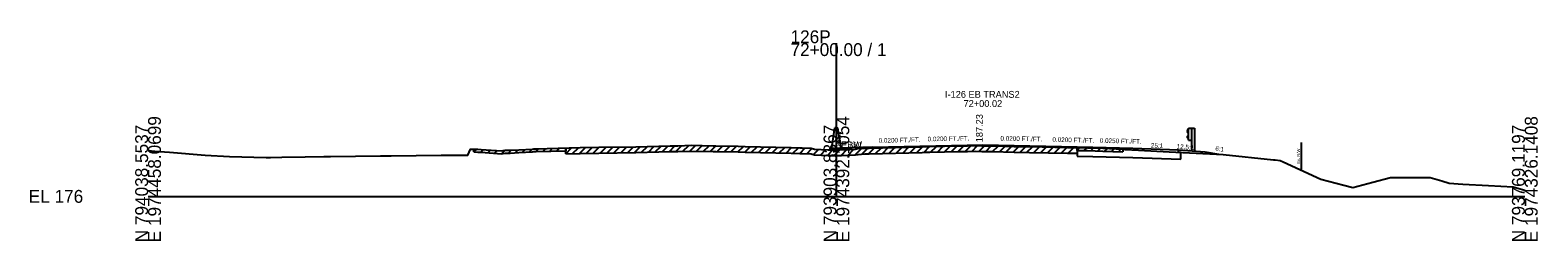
# Model space of a CAD drawing. Extents: x -161 to 1970889, y -4362 to 797231.
# Drawn here: x 2974.3 to 3302.8, y 4490.3 to 4536.2 of the extents above; entities that cross this region are included whole.
import ezdxf

# ---------------------------------------------------------------- set-up
doc = ezdxf.new("R2010")
doc.units = 0
for name, color, linetype in [('RD_GPK_XS_Cell', 7, 'Continuous'), ('RD_XS_Base', 7, 'Continuous'), ('RD_XS_EarthShd', 7, 'Continuous'), ('RD_XS_ExGround', 7, 'Continuous'), ('RD_XS_ExPaveRet', 7, 'Continuous'), ('RD_XS_ExRW', 7, 'Continuous'), ('RD_XS_GR', 7, 'Continuous'), ('RD_XS_MedBWall', 7, 'Continuous'), ('RD_XS_Misc_Line', 7, 'Continuous'), ('RD_XS_Pave', 7, 'Continuous'), ('RD_XS_PaveOvlay', 7, 'Continuous'), ('RD_XS_PaveShd', 7, 'Continuous'), ('RD_XS_TieSlope', 7, 'Continuous'), ('RD_XS_TX_Elev_EX', 7, 'Continuous'), ('RD_XS_TX_Elev_PR', 7, 'Continuous'), ('RD_XS_TX_MkPT', 7, 'Continuous'), ('RD_XS_TX_Profile', 7, 'Continuous'), ('RD_XS_TX_ShdSlope', 7, 'Continuous'), ('RD_XS_TX_Slope', 7, 'Continuous'), ('RD_XS_TX_Station', 7, 'Continuous')]:
    doc.layers.add(name, color=color, linetype=linetype)

msp = doc.modelspace()

# ---------------------------------------------------------------- linework, layer by layer
at = {"layer": 'RD_GPK_XS_Cell'}
for p, q in [((3150, 4500), (3150, 4533.38)), ((3000, 4500), (3150, 4500)), ((3150, 4500), (3300, 4500))]:
    msp.add_line(p, q, dxfattribs=at)
at = {"layer": 'RD_XS_Base'}
for p, q in [((3202.43, 4508.78), (3205.9, 4508.71)), ((3205.9, 4508.71), (3214.56, 4508.5)), ((3214.56, 4508.5), (3225.06, 4508.08)), ((3224.56, 4509.58), (3224.56, 4510.14)), ((3225.06, 4509.56), (3224.56, 4509.58)), ((3225.06, 4508.08), (3225.06, 4509.56))]:
    msp.add_line(p, q, dxfattribs=at)
at = {"layer": 'RD_XS_EarthShd'}
msp.add_line((3224.56, 4510.14), (3226.56, 4509.98), dxfattribs=at)
at = {"layer": 'RD_XS_ExGround'}
msp.add_lwpolyline([(3000, 4510.01), (3001.49, 4509.88), (3004.65, 4509.64), (3012.41, 4508.96), (3017.74, 4508.71), (3025.72, 4508.46), (3026.32, 4508.44), (3026.66, 4508.45), (3029.13, 4508.58), (3034.2, 4508.62), (3038.27, 4508.69), (3039.75, 4508.71), (3050.68, 4508.84), (3051.47, 4508.84), (3053, 4508.86), (3063.84, 4508.96), (3066.91, 4508.97), (3069.71, 4508.98), (3070.23, 4510.29), (3071.09, 4510.29), (3071.83, 4510.28), (3072.59, 4510.23), (3077.02, 4509.92), (3077.38, 4509.99), (3077.78, 4510.07), (3078.09, 4510.07), (3078.89, 4510.07), (3080.78, 4510.16), (3083.75, 4510.29), (3084.03, 4510.38), (3084.56, 4510.39), (3094.16, 4510.62), (3098.2, 4510.69), (3106.26, 4510.82), (3113.8, 4511), (3114.97, 4511.03), (3115.42, 4511.04), (3118.39, 4511.13), (3123.12, 4511.03), (3123.7, 4511.01), (3128.59, 4510.93), (3130.12, 4510.89), (3140.1, 4510.65), (3142.01, 4510.6), (3142.53, 4510.57), (3144.48, 4510.49), (3145.19, 4510.3), (3148.19, 4510.17), (3149.17, 4510.16), (3150, 4510.17), (3151.13, 4510.18), (3152.91, 4510.23), (3154.14, 4510.27), (3154.7, 4510.41), (3156.2, 4510.5), (3157.14, 4510.54), (3168.66, 4510.83), (3169.48, 4510.85), (3170.38, 4510.87), (3176.71, 4511.01), (3178.58, 4511.04), (3180.39, 4511.07), (3181.67, 4511.05), (3184.03, 4511), (3188.71, 4510.9), (3192.09, 4510.84), (3200.32, 4510.68), (3204.71, 4510.6), (3208.07, 4510.47), (3212.43, 4510.32), (3212.86, 4510.21), (3215.83, 4510.07), (3222.47, 4509.71), (3234.24, 4509.15), (3245.25, 4507.99), (3245.63, 4507.95), (3246.7, 4507.84), (3247.37, 4507.54), (3255.52, 4503.74), (3260.57, 4502.42), (3262.53, 4501.94), (3266.86, 4503.1), (3270.71, 4504.13), (3272.89, 4504.14), (3279.35, 4504.13), (3281.89, 4503.39), (3283.52, 4502.9), (3286.5, 4502.69), (3292.1, 4502.35), (3297.44, 4502.08), (3300, 4501.35)], dxfattribs=at)
at = {"layer": 'RD_XS_ExPaveRet'}
for p, q in [((3071.02, 4509.67), (3071.02, 4510.29)), ((3071.02, 4509.67), (3071.09, 4509.67)), ((3071.09, 4509.67), (3071.83, 4509.66)), ((3071.83, 4509.66), (3072.59, 4509.6)), ((3072.59, 4509.6), (3077.02, 4509.3)), ((3077.02, 4509.3), (3077.38, 4509.36)), ((3077.38, 4509.36), (3077.78, 4509.44)), ((3077.78, 4509.44), (3078.09, 4509.45)), ((3078.09, 4509.45), (3078.89, 4509.45)), ((3078.89, 4509.45), (3080.78, 4509.53)), ((3080.78, 4509.53), (3083.75, 4509.67)), ((3083.75, 4509.67), (3084.03, 4509.75)), ((3084.03, 4509.75), (3084.56, 4509.77)), ((3084.56, 4509.77), (3091.02, 4509.92)), ((3091.02, 4509.29), (3091.02, 4510.54)), ((3091.02, 4510.54), (3091.02, 4509.92)), ((3091.02, 4509.29), (3094.16, 4509.37)), ((3094.16, 4509.37), (3098.2, 4509.44)), ((3098.2, 4509.44), (3106.26, 4509.57)), ((3106.26, 4509.57), (3113.8, 4509.75)), ((3113.8, 4509.75), (3114.97, 4509.78)), ((3114.97, 4509.78), (3115.42, 4509.79)), ((3115.42, 4509.79), (3118.39, 4509.88)), ((3118.39, 4509.88), (3123.12, 4509.78)), ((3123.12, 4509.78), (3123.7, 4509.76)), ((3123.7, 4509.76), (3128.59, 4509.68)), ((3128.59, 4509.68), (3130.12, 4509.64)), ((3130.12, 4509.64), (3140.1, 4509.4)), ((3140.1, 4509.4), (3142.01, 4509.35)), ((3142.01, 4509.35), (3142.53, 4509.32)), ((3142.53, 4509.32), (3144.48, 4509.24)), ((3144.48, 4509.24), (3145.19, 4509.05)), ((3145.19, 4509.05), (3148.19, 4508.92)), ((3148.19, 4508.92), (3149.17, 4508.91)), ((3149.17, 4508.91), (3150, 4508.92)), ((3150, 4508.92), (3151.13, 4508.93)), ((3151.13, 4508.93), (3152.91, 4508.98)), ((3152.91, 4508.98), (3154.14, 4509.02)), ((3154.14, 4509.02), (3154.7, 4509.16)), ((3154.7, 4509.16), (3156.2, 4509.25)), ((3156.2, 4509.25), (3157.14, 4509.29)), ((3157.14, 4509.29), (3168.66, 4509.58)), ((3168.66, 4509.58), (3169.48, 4509.6)), ((3169.48, 4509.6), (3170.38, 4509.62)), ((3170.38, 4509.62), (3176.71, 4509.76)), ((3176.71, 4509.76), (3178.58, 4509.79)), ((3178.58, 4509.79), (3180.39, 4509.82)), ((3180.39, 4509.82), (3181.67, 4509.8)), ((3181.67, 4509.8), (3184.03, 4509.75)), ((3184.03, 4509.75), (3188.71, 4509.65)), ((3188.71, 4509.65), (3192.09, 4509.59)), ((3192.09, 4509.59), (3200.32, 4509.43)), ((3200.32, 4509.43), (3202.43, 4509.39)), ((3202.43, 4510.64), (3202.43, 4509.39)), ((3202.43, 4510.02), (3202.43, 4510.64)), ((3202.43, 4510.02), (3204.71, 4509.97)), ((3204.71, 4509.97), (3208.07, 4509.85)), ((3208.07, 4509.85), (3212.43, 4509.69)), ((3212.43, 4510.32), (3212.43, 4509.69))]:
    msp.add_line(p, q, dxfattribs=at)
at = {"layer": 'RD_XS_ExRW'}
msp.add_line((3251.25, 4511.73), (3251.25, 4505.73), dxfattribs=at)
at = {"layer": 'RD_XS_GR'}
for p, q in [((3226.7, 4514.69), (3226.43, 4514.25)), ((3226.43, 4514.25), (3226.43, 4514.14)), ((3226.43, 4514.14), (3226.7, 4513.7)), ((3226.7, 4514.85), (3227.37, 4514.85)), ((3226.7, 4512.28), (3226.7, 4514.85)), ((3227.37, 4514.85), (3228.04, 4514.85)), ((3227.37, 4514.85), (3227.37, 4509.91)), ((3228.04, 4514.85), (3228.04, 4509.8)), ((3226.43, 4512.99), (3226.7, 4513.43)), ((3226.43, 4512.88), (3226.43, 4512.99)), ((3226.7, 4512.44), (3226.43, 4512.88)), ((3226.7, 4512.28), (3227.37, 4512.28))]:
    msp.add_line(p, q, dxfattribs=at)
at = {"layer": 'RD_XS_MedBWall'}
for p, q in [((3148.96, 4510.16), (3149.67, 4514.94)), ((3150, 4514.94), (3149.67, 4514.94)), ((3150, 4514.94), (3150.33, 4514.94)), ((3151, 4510.46), (3150.33, 4514.94))]:
    msp.add_line(p, q, dxfattribs=at)
at = {"layer": 'RD_XS_Misc_Line'}
for p, q in [((3101.52, 4509.5), (3102.79, 4510.77)), ((3103.02, 4509.52), (3104.29, 4510.79)), ((3104.52, 4509.55), (3105.79, 4510.82)), ((3106.02, 4509.57), (3107.29, 4510.85)), ((3107.52, 4509.6), (3108.8, 4510.88)), ((3109.02, 4509.64), (3110.3, 4510.92)), ((3110.52, 4509.67), (3111.8, 4510.95)), ((3112.02, 4509.71), (3113.3, 4510.99)), ((3113.52, 4509.74), (3114.8, 4511.02)), ((3115.02, 4509.78), (3116.3, 4511.07)), ((3116.52, 4509.82), (3117.8, 4511.11)), ((3118.02, 4509.87), (3119.26, 4511.11)), ((3119.52, 4509.85), (3120.74, 4511.08)), ((3121.02, 4509.82), (3122.24, 4511.05)), ((3122.52, 4509.79), (3123.74, 4511.01)), ((3124.02, 4509.76), (3125.24, 4510.99)), ((3125.52, 4509.73), (3126.74, 4510.96)), ((3127.02, 4509.7), (3128.24, 4510.93)), ((3128.52, 4509.68), (3129.74, 4510.9)), ((3130.02, 4509.64), (3131.24, 4510.86)), ((3131.52, 4509.61), (3132.74, 4510.83)), ((3133.02, 4509.57), (3134.24, 4510.79)), ((3134.52, 4509.53), (3135.74, 4510.75)), ((3164.52, 4509.48), (3165.8, 4510.76)), ((3166.02, 4509.52), (3167.3, 4510.8)), ((3167.52, 4509.55), (3168.8, 4510.84)), ((3169.02, 4509.59), (3170.29, 4510.87)), ((3170.52, 4509.63), (3171.79, 4510.9)), ((3172.02, 4509.66), (3173.29, 4510.93)), ((3173.52, 4509.69), (3174.79, 4510.96)), ((3175.02, 4509.72), (3176.29, 4511)), ((3176.52, 4509.75), (3177.79, 4511.03)), ((3178.02, 4509.78), (3179.29, 4511.05)), ((3179.52, 4509.81), (3180.77, 4511.07)), ((3181.02, 4509.81), (3182.24, 4511.04)), ((3182.52, 4509.78), (3183.74, 4511)), ((3184.02, 4509.75), (3185.24, 4510.97)), ((3185.52, 4509.72), (3186.74, 4510.94)), ((3187.02, 4509.69), (3188.24, 4510.91)), ((3188.52, 4509.66), (3189.74, 4510.88)), ((3190.02, 4509.63), (3191.24, 4510.85)), ((3191.52, 4509.6), (3192.74, 4510.83)), ((3193.02, 4509.57), (3194.24, 4510.8)), ((3194.52, 4509.54), (3195.74, 4510.77)), ((3071.02, 4509.67), (3071.63, 4510.28)), ((3072.52, 4509.61), (3073.1, 4510.19)), ((3074.02, 4509.51), (3074.6, 4510.09)), ((3075.52, 4509.4), (3076.1, 4509.99)), ((3077.02, 4509.3), (3077.79, 4510.07)), ((3078.52, 4509.45), (3079.15, 4510.09)), ((3080.02, 4509.5), (3080.67, 4510.15)), ((3081.52, 4509.57), (3082.17, 4510.22)), ((3083.02, 4509.63), (3083.67, 4510.29)), ((3084.52, 4509.77), (3085.16, 4510.41)), ((3086.02, 4509.8), (3086.66, 4510.44)), ((3087.52, 4509.84), (3088.16, 4510.48)), ((3089.02, 4509.87), (3089.66, 4510.51)), ((3091.02, 4509.29), (3092.3, 4510.57)), ((3092.52, 4509.33), (3093.8, 4510.61)), ((3094.02, 4509.36), (3095.29, 4510.64)), ((3095.52, 4509.39), (3096.79, 4510.67)), ((3097.02, 4509.42), (3098.29, 4510.69)), ((3098.52, 4509.45), (3099.79, 4510.72)), ((3100.02, 4509.47), (3101.29, 4510.74)), ((3136.02, 4509.5), (3137.24, 4510.72)), ((3137.52, 4509.46), (3138.74, 4510.68)), ((3139.02, 4509.42), (3140.24, 4510.65)), ((3140.52, 4509.39), (3141.73, 4510.61)), ((3142.02, 4509.35), (3143.21, 4510.55)), ((3143.52, 4509.28), (3144.67, 4510.44)), ((3145.02, 4509.1), (3146.17, 4510.26)), ((3146.52, 4508.99), (3147.71, 4510.19)), ((3148.02, 4508.93), (3149.25, 4510.16)), ((3149.52, 4508.91), (3150.78, 4510.18)), ((3151.02, 4508.93), (3152.3, 4510.21)), ((3152.52, 4508.97), (3153.8, 4510.26)), ((3154.02, 4509.01), (3155.46, 4510.46)), ((3155.52, 4509.21), (3156.84, 4510.53)), ((3157.02, 4509.29), (3158.3, 4510.57)), ((3158.52, 4509.33), (3159.8, 4510.61)), ((3160.02, 4509.37), (3161.3, 4510.65)), ((3161.52, 4509.4), (3162.8, 4510.69)), ((3163.02, 4509.44), (3164.3, 4510.72)), ((3196.02, 4509.51), (3197.24, 4510.74)), ((3197.52, 4509.48), (3198.74, 4510.71)), ((3199.02, 4509.46), (3200.24, 4510.68)), ((3200.52, 4509.43), (3201.74, 4510.65)), ((3202.43, 4510.02), (3203.05, 4510.63)), ((3203.93, 4509.99), (3204.55, 4510.6)), ((3205.43, 4509.95), (3206.04, 4510.55)), ((3206.93, 4509.89), (3207.54, 4510.49)), ((3208.43, 4509.83), (3209.04, 4510.44)), ((3209.93, 4509.78), (3210.54, 4510.39)), ((3211.43, 4509.73), (3212.04, 4510.33))]:
    msp.add_line(p, q, dxfattribs=at)
at = {"layer": 'RD_XS_Pave'}
for p, q in [((3157.9, 4510.75), (3181.9, 4511.23)), ((3181.9, 4511.23), (3205.9, 4510.75)), ((3205.9, 4510.75), (3214.56, 4510.54))]:
    msp.add_line(p, q, dxfattribs=at)
at = {"layer": 'RD_XS_PaveOvlay'}
for p, q in [((3157.14, 4510.54), (3168.66, 4510.83)), ((3168.66, 4510.83), (3169.48, 4510.85)), ((3169.48, 4510.85), (3170.38, 4510.87)), ((3170.38, 4510.87), (3176.71, 4511.01)), ((3176.71, 4511.01), (3178.58, 4511.04)), ((3178.58, 4511.04), (3180.39, 4511.07)), ((3180.39, 4511.07), (3181.67, 4511.05)), ((3181.67, 4511.05), (3184.03, 4511)), ((3184.03, 4511), (3188.71, 4510.9)), ((3188.71, 4510.9), (3192.09, 4510.84)), ((3192.09, 4510.84), (3200.32, 4510.68)), ((3150, 4510.17), (3151.13, 4510.18)), ((3151.13, 4510.18), (3152.91, 4510.23)), ((3152.91, 4510.23), (3154.14, 4510.27)), ((3154.14, 4510.27), (3154.7, 4510.41)), ((3154.7, 4510.41), (3156.2, 4510.5)), ((3156.2, 4510.5), (3157.14, 4510.54)), ((3200.32, 4510.68), (3202.43, 4510.64)), ((3202.43, 4510.64), (3202.43, 4508.78))]:
    msp.add_line(p, q, dxfattribs=at)
at = {"layer": 'RD_XS_PaveShd'}
for p, q in [((3157.9, 4510.75), (3148.99, 4510.4)), ((3214.56, 4510.54), (3224.56, 4510.14))]:
    msp.add_line(p, q, dxfattribs=at)
at = {"layer": 'RD_XS_TieSlope'}
for p, q in [((3226.56, 4509.98), (3230.31, 4509.68)), ((3230.31, 4509.68), (3233.22, 4509.2))]:
    msp.add_line(p, q, dxfattribs=at)

# ---------------------------------------------------------------- texts
at = {"layer": 'RD_GPK_XS_Cell'}
for s, p in [('126P', (3140, 4533.38)), ('72+00.00 / 1', (3140, 4530.58)), ('EL 176', (2974, 4498.6))]:
    msp.add_text(s, height=2.8, dxfattribs=at).set_placement(p)
for s, p in [('E 1974392.1054', (3152.8, 4490)), ('N 794038.5537', (3000, 4490)), ('E 1974458.0699', (3002.8, 4490)), ('N 793903.8367', (3150, 4490)), ('N 793769.1197', (3300, 4490)), ('E 1974326.1408', (3302.8, 4490))]:
    msp.add_text(s, height=2.8, rotation=90, dxfattribs=at).set_placement(p)
at = {"layer": 'RD_XS_ExRW'}
msp.add_text('Ex. R/W ', height=0.65, rotation=90, dxfattribs=at).set_placement((3251, 4507.12))
at = {"layer": 'RD_XS_TX_Elev_EX'}
msp.add_text('186.17', height=1, rotation=90, dxfattribs=at).set_placement((3151, 4510.17))
at = {"layer": 'RD_XS_TX_Elev_PR'}
msp.add_text(' 187.23', height=1.5, rotation=90, dxfattribs=at).set_placement((3181.9, 4511.23))
at = {"layer": 'RD_XS_TX_MkPT'}
msp.add_text('EBW', height=1.5, dxfattribs=at).set_placement((3151, 4510.46))
at = {"layer": 'RD_XS_TX_Profile'}
for rotation, p in [(2.2905, (3152.89, 4510.8)), (357.7095, (3218.51, 4510.63))]:
    msp.add_text('25:1', height=1, rotation=rotation, dxfattribs=at).set_placement(p)
at = {"layer": 'RD_XS_TX_ShdSlope'}
msp.add_text('12.5:1', height=1, rotation=355.4264, dxfattribs=at).set_placement((3224.1, 4510.42))
at = {"layer": 'RD_XS_TX_Slope'}
for s, rotation, p in [('0.0200 FT./FT.', 1.1458, (3159.2, 4511.67)), ('0.0200 FT./FT.', 1.1443, (3169.88, 4511.99)), ('0.0200 FT./FT.', 358.853, (3185.73, 4512.16)), ('0.0200 FT./FT.', 358.5681, (3197.05, 4511.91)), ('0.0250 FT./FT.', 358.569, (3207.38, 4511.68)), ('6:1', 350.5383, (3232.5, 4510.01))]:
    msp.add_text(s, height=1, rotation=rotation, dxfattribs=at).set_placement(p)
at = {"layer": 'RD_XS_TX_Station'}
for s, p in [('I-126 EB TRANS2', (3173.65, 4521.48)), ('72+00.02', (3177.7, 4519.48))]:
    msp.add_text(s, height=1.5, dxfattribs=at).set_placement(p)

doc.saveas('drawing.dxf')
